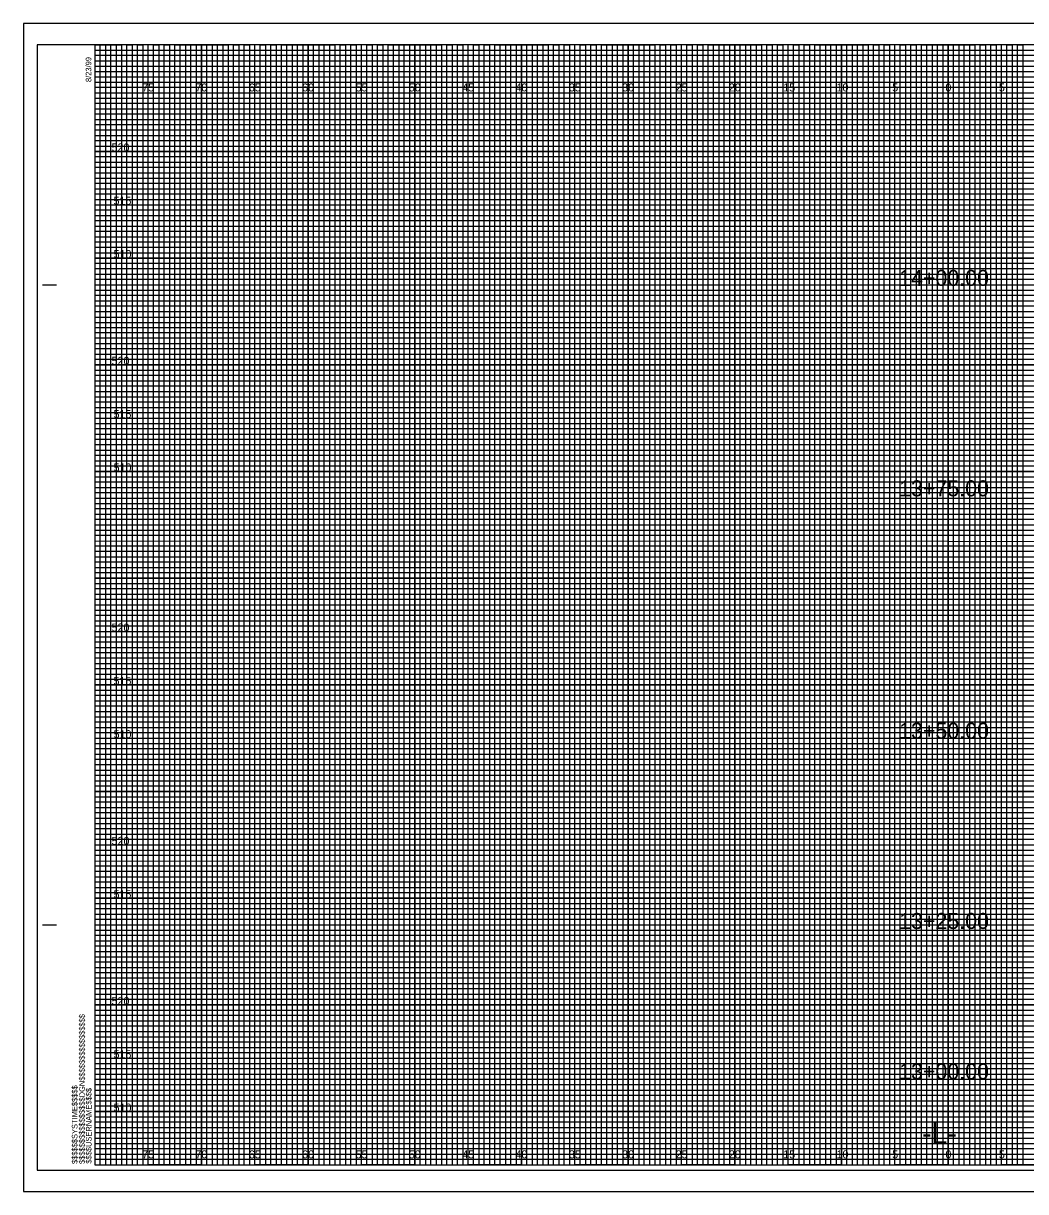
# Model space of a CAD drawing. Extents: x -7 to 181, y -2 to 107.
# Drawn here: x -6.7 to 87.2, y -2.5 to 107 of the extents above; entities that cross this region are included whole.
import ezdxf

# ---------------------------------------------------------------- set-up
doc = ezdxf.new("R2010")
doc.units = 0
for name, color, linetype in [('Prop XS Alignment Label', 7, 'Continuous'), ('Prop XS Elevation Labels', 7, 'Continuous'), ('Prop XS Offset Labels', 7, 'Continuous'), ('Prop XS Station Labels', 7, 'Continuous'), ('Sheet Cross Section CELL', 7, 'Continuous'), ('Sheet Cross Section Grid Major CELL', 7, 'Continuous'), ('Sheet Cross Section Grid Middle CELL', 7, 'Continuous'), ('Sheet Cross Section Grid Minor 1 CELL', 7, 'Continuous'), ('Sheet Cross Section Grid Minor 2 CELL', 7, 'Continuous'), ('Sheet Cutting Line CELL', 7, 'Continuous'), ('Sheet DOT Grid CELL', 7, 'Continuous'), ('Sheet Plot Border Inside CELL', 7, 'Continuous'), ('Sheet Plot Border Outside CELL', 7, 'Continuous')]:
    doc.layers.add(name, color=color, linetype=linetype)

msp = doc.modelspace()

# ---------------------------------------------------------------- linework, layer by layer
at = {"layer": 'Sheet Cross Section CELL'}
for p, q in [((-4.9, 82.5), (-3.65, 82.5)), ((-4.85, 82.5), (-3.6, 82.5)), ((-4.9, 22.5), (-3.65, 22.5)), ((-4.85, 22.5), (-3.6, 22.5)), ((0, 0), (0, 0)), ((0, 0), (0, 0)), ((0, 0), (0, 0)), ((0, 0), (0, 0)), ((0, 0), (0, 0)), ((0, 0), (0, 0)), ((0, 0), (0, 0))]:
    msp.add_line(p, q, dxfattribs=at)
msp.add_lwpolyline([(160, 105), (0, 105), (0, 0), (160, 0)], close=True, dxfattribs=at)
at = {"layer": 'Sheet Cross Section Grid Major CELL'}
for p, q in [((5, 105), (0, 105)), ((5, 0), (5, 105)), ((15, 105), (10, 105)), ((10, 105), (10, 0)), ((15, 0), (15, 105)), ((25, 105), (20, 105)), ((20, 105), (20, 0)), ((25, 0), (25, 105)), ((35, 105), (30, 105)), ((30, 105), (30, 0)), ((35, 0), (35, 105)), ((45, 105), (40, 105)), ((40, 105), (40, 0)), ((45, 0), (45, 105)), ((55, 105), (50, 105)), ((50, 105), (50, 0)), ((55, 0), (55, 105)), ((65, 105), (60, 105)), ((60, 105), (60, 0)), ((65, 0), (65, 105)), ((75, 105), (70, 105)), ((70, 105), (70, 0)), ((75, 0), (75, 105)), ((85, 105), (80, 105)), ((80, 105), (80, 0)), ((85, 0), (85, 105)), ((10, 0), (5, 0)), ((20, 0), (15, 0)), ((30, 0), (25, 0)), ((40, 0), (35, 0)), ((50, 0), (45, 0)), ((60, 0), (55, 0)), ((70, 0), (65, 0)), ((80, 0), (75, 0)), ((90, 0), (85, 0))]:
    msp.add_line(p, q, dxfattribs=at)
for points in [[(0, 100), (160, 100), (160, 95), (0, 95)], [(0, 90), (160, 90), (160, 85), (0, 85)], [(0, 80), (160, 80), (160, 75), (0, 75)], [(0, 70), (160, 70), (160, 65), (0, 65)], [(0, 60), (160, 60), (160, 55), (0, 55)], [(0, 50), (160, 50), (160, 45), (0, 45)], [(0, 40), (160, 40), (160, 35), (0, 35)], [(0, 30), (160, 30), (160, 25), (0, 25)], [(0, 20), (160, 20), (160, 15), (0, 15)], [(0, 10), (160, 10), (160, 5), (0, 5)]]:
    msp.add_lwpolyline(points, dxfattribs=at)
at = {"layer": 'Sheet Cross Section Grid Middle CELL'}
for points in [[(0, 105), (2.5, 105), (2.5, 0), (7.5, 0), (7.5, 105), (12.5, 105), (12.5, 0), (17.5, 0), (17.5, 105), (22.5, 105), (22.5, 0), (27.5, 0), (27.5, 105), (32.5, 105), (32.5, 0), (37.5, 0), (37.5, 105), (42.5, 105), (42.5, 0), (47.5, 0), (47.5, 105), (52.5, 105), (52.5, 0), (57.5, 0), (57.5, 105), (62.5, 105), (62.5, 0), (67.5, 0), (67.5, 105), (72.5, 105), (72.5, 0), (77.5, 0), (77.5, 105), (82.5, 105), (82.5, 0), (87.5, 0)], [(0, 102.5), (137.5, 102.5)], [(0, 92.5), (160, 92.5), (160, 97.5), (0, 97.5)], [(0, 82.5), (160, 82.5), (160, 87.5), (0, 87.5)], [(0, 72.5), (160, 72.5), (160, 77.5), (0, 77.5)], [(0, 62.5), (160, 62.5), (160, 67.5), (0, 67.5)], [(0, 52.5), (160, 52.5), (160, 57.5), (0, 57.5)], [(0, 42.5), (160, 42.5), (160, 47.5), (0, 47.5)], [(0, 32.5), (160, 32.5), (160, 37.5), (0, 37.5)], [(0, 22.5), (160, 22.5), (160, 27.5), (0, 27.5)], [(0, 12.5), (160, 12.5), (160, 17.5), (0, 17.5)], [(0, 2.5), (160, 2.5), (160, 7.5), (0, 7.5)]]:
    msp.add_lwpolyline(points, dxfattribs=at)
at = {"layer": 'Sheet Cross Section Grid Minor 1 CELL'}
for p, q in [((0, 104.5), (130, 104.5)), ((130, 103.99), (0, 103.99)), ((0, 103.99), (0, 103.5)), ((0, 103.5), (130, 103.5)), ((130, 102.95), (0, 102.95)), ((0, 102.95), (0, 102)), ((0, 102), (160, 102))]:
    msp.add_line(p, q, dxfattribs=at)
for points in [[(0, 101.5), (135, 101.5), (160, 101.5), (160, 101), (0, 101)], [(0, 100.5), (160, 100.5), (160, 99.5), (0, 99.5)], [(0, 99), (160, 99), (160, 98.5), (0, 98.49)], [(0, 98), (160, 98), (160, 97), (0, 97)], [(0, 96.5), (160, 96.5), (160, 96), (0, 96)], [(0, 95.5), (160, 95.5), (160, 94.5), (0, 94.5)], [(0, 94), (160, 94), (160, 93.5), (0, 93.5)], [(0, 93), (160, 93), (160, 92), (0, 92)], [(0, 91.5), (160, 91.5), (160, 91), (0, 91)], [(0, 90.5), (160, 90.5), (160, 89.5), (0, 89.5)], [(0, 89), (160, 89), (160, 88.5), (0, 88.5)], [(0, 88), (160, 88), (160, 86.98), (160, 86.5), (160, 86), (0, 86)], [(0, 87), (160, 87), (160, 86.5), (0, 86.5)], [(0, 85.5), (160, 85.5), (160, 84.5), (0, 84.52)], [(0, 84.52), (160, 84.5), (160, 84), (0, 84)], [(0, 83.5), (160, 83.5), (160, 83), (0, 83)], [(0, 82), (160, 82), (160, 81.5), (0, 81.5)], [(0, 81), (160, 81), (160, 80.5), (0, 80.5)], [(-0.04, 79.45), (160, 79.45), (160, 78.94), (-0.04, 78.94)], [(0, 78.5), (160, 78.5), (160, 78), (0, 78)], [(0, 77), (160, 77), (160, 76.5), (0, 76.5)], [(0, 76), (160, 76), (160, 75.5), (0, 75.5)], [(0, 74.5), (160, 74.5), (160, 74), (0, 74)], [(0, 73.5), (160, 73.5), (160, 73), (0, 73)], [(0, 72), (160, 72), (160, 71.5), (0, 71.5)], [(0, 71), (160, 71), (160, 70.5), (0, 70.5)], [(0, 69.5), (160, 69.5), (160, 68.99), (0, 69)], [(0, 68.5), (160, 68.5), (160, 68), (0, 68)], [(0, 67), (160, 67), (160, 66.5), (0, 66.5)], [(0, 66), (160, 66), (160, 65.5), (0, 65.5)], [(0, 64.5), (160, 64.5), (160, 64), (0, 64)], [(0, 63.5), (160, 63.5), (160, 63), (0, 63)], [(0, 62), (160, 62), (160, 61.5), (0, 61.5)], [(0, 61), (160, 61), (160, 60.5), (0, 60.5)], [(0, 59.5), (160, 59.5), (160, 59), (0, 59)], [(0, 58.5), (160.03, 58.45), (160, 58), (0, 58)], [(0, 57), (160, 57), (160, 56.5), (0, 56.5)], [(0, 56), (160, 56), (160, 55.5), (0, 55.5)], [(0, 54.5), (160, 54.5), (160, 54), (0, 54)], [(0, 53.5), (160, 53.5), (160, 53), (0, 53)], [(0, 52), (160, 52), (160, 51.5), (0, 51.5)], [(0, 51), (160, 51), (160, 50.5), (0, 50.5)], [(0, 49.5), (160, 49.5), (160, 49), (0, 49)], [(0, 48.5), (160, 48.5), (160, 48), (0, 48)], [(0, 47), (160, 47), (160, 46.5), (0, 46.5)], [(0, 46), (160, 46), (160, 45.5), (0, 45.5)], [(0, 44.5), (160, 44.5), (160, 44), (0, 44)], [(0, 43.5), (160, 43.5), (160, 43), (0, 43)], [(0, 42), (160, 42), (160, 41.5), (0, 41.5)], [(0, 41), (160, 41), (160, 40.5), (0, 40.5)], [(0, 39.5), (160, 39.5), (160, 38.99), (0, 39)], [(0, 38.5), (160, 38.5), (160, 38), (0, 38)], [(0, 37), (160, 37), (160, 36.5), (0, 36.5)], [(0, 36), (160, 36), (160, 35.5), (0, 35.5)], [(0, 34.5), (160, 34.5), (160, 34), (0, 34)], [(0, 33.5), (160, 33.5), (160, 33), (0, 33)], [(0, 32), (160, 32), (160, 31.5), (0, 31.5)], [(0, 31), (160, 31), (160, 30.5), (0, 30.5)], [(0, 29.5), (160, 29.5), (160, 29), (0, 29)], [(0, 28.5), (160.03, 28.46), (160, 28), (0, 28)], [(0, 27), (160, 27), (160, 26.5), (0, 26.5)], [(0, 26), (160, 26), (160, 25.5), (0, 25.5)], [(0, 24.5), (160, 24.5), (160, 24), (0, 24)], [(0, 23.5), (160, 23.5), (160, 23), (0, 23)], [(0, 22), (160, 22), (160, 21.5), (0, 21.5)], [(0, 21), (160, 21), (160, 20.5), (0, 20.5)], [(0, 19.5), (160, 19.5), (160, 19), (0, 19)], [(0, 18.5), (160, 18.5), (160, 18), (0, 18)], [(0, 17), (160, 17), (160, 16.5), (0, 16.5)], [(0, 16), (160, 16), (160, 15.5), (0, 15.5)], [(0, 14.5), (160, 14.5), (160, 14), (0, 14)], [(0, 13.5), (160, 13.5), (160, 13), (0, 13)], [(0, 12), (160, 12), (160, 11.5), (0, 11.5)], [(0, 11), (160, 11), (160, 10.5), (0, 10.5)], [(0, 9.5), (160, 9.5), (160, 9), (0, 9)], [(0, 8.5), (160, 8.5), (160, 8), (0, 8)], [(0, 7), (160, 7), (160, 6.5), (0, 6.5)], [(0, 6), (160, 6), (160, 5.5), (0, 5.5)], [(0, 4.5), (160, 4.5), (160, 4), (0, 4)], [(0, 3.5), (160, 3.5), (160, 3), (0, 3)], [(0, 2), (160, 2), (160, 1.5), (0, 1.5)], [(0, 1), (160, 1), (160, 0.5), (0, 0.5)]]:
    msp.add_lwpolyline(points, dxfattribs=at)
at = {"layer": 'Sheet Cross Section Grid Minor 2 CELL'}
for points in [[(0, 0), (0.5, 0), (0.5, 105), (1, 105), (1, 0)], [(1, 0), (1.5, 0), (1.5, 105), (2, 105), (2, 0)], [(2.5, 0), (3, 0), (3, 105), (3.5, 105), (3.5, 0)], [(3.5, 0), (4, 0), (4, 105), (4.5, 105), (4.5, 0)], [(5, 0), (5.5, 0), (5.5, 105), (6, 105), (6, 0)], [(6, 0), (6.5, 0), (6.5, 105), (7, 105), (7, 0)], [(7.5, 0), (8, 0), (8, 105), (8.5, 105), (8.5, 0)], [(8.5, 0), (9, 0), (9, 105), (9.5, 105), (9.5, 0)], [(10, 0), (10.5, 0), (10.5, 105), (11, 105), (11, 0)], [(11, 0), (11.5, 0), (11.5, 105), (12, 105), (12, 0)], [(12.5, 0), (13, 0), (13, 105), (13.5, 105), (13.5, 0)], [(13.5, 0), (14, 0), (14, 105), (14.5, 105), (14.5, 0)], [(15, 0), (15.5, 0), (15.5, 105), (16, 105), (16, 0)], [(16, 0), (16.5, 0), (16.5, 105), (17, 105), (17, 0)], [(17.5, 0), (18, 0), (18, 105), (18.5, 105), (18.5, 0)], [(18.5, 0), (19, 0), (19, 105), (19.5, 105), (19.5, 0)], [(20, 0), (20.5, 0), (20.5, 105), (21, 105), (21, 0)], [(21, 0), (21.5, 0), (21.5, 105), (22, 105), (22, 0)], [(22.5, 0), (23, 0), (23, 105), (23.5, 105), (23.5, 0)], [(23.5, 0), (24, 0), (24, 105), (24.5, 105), (24.5, 0)], [(25, 0), (25.5, 0), (25.5, 105), (26, 105), (26, 0)], [(26, 0), (26.5, 0), (26.5, 105), (27, 105), (27, 0)], [(27.5, 0), (28, 0), (28, 105), (28.5, 105), (28.5, 0)], [(28.5, 0), (29, 0), (29, 105), (29.5, 105), (29.5, 0)], [(30, 0), (30.5, 0), (30.5, 105), (31, 105), (31, 0)], [(31, 0), (31.5, 0), (31.5, 105), (32, 105), (32, 0)], [(32.5, 0), (33, 0), (33, 105), (33.5, 105), (33.5, 0)], [(33.5, 0), (34, 0), (34, 105), (34.5, 105), (34.5, 0)], [(35, 0), (35.5, 0), (35.5, 105), (36, 105), (36, 0)], [(36, 0), (36.5, 0), (36.5, 105), (37, 105), (37, 0)], [(37.5, 0), (38, 0), (38, 105), (38.5, 105), (38.5, 0)], [(38.5, 0), (39, 0), (39, 105), (39.5, 105), (39.5, 0)], [(40, 0), (40.5, 0), (40.5, 105), (41, 105), (41, 0)], [(41, 0), (41.5, 0), (41.5, 105), (42, 105), (42, 0)], [(42.5, 0), (43, 0), (43, 105), (43.5, 105), (43.5, 0)], [(43.5, 0), (44, 0), (44, 105), (44.5, 105), (44.5, 0)], [(45, 0), (45.5, 0), (45.5, 105), (46, 105), (46, 0)], [(46, 0), (46.5, 0), (46.5, 105), (47, 105), (47, 0)], [(47.5, 0), (48, 0), (48, 105), (48.5, 105), (48.5, 0)], [(48.5, 0), (49, 0), (49, 105), (49.5, 105), (49.5, 0)], [(50, 0), (50.5, 0), (50.5, 105), (51, 105), (51, 0)], [(51, 0), (51.5, 0), (51.5, 105), (52, 105), (52, 0)], [(52.5, 0), (53, 0), (53, 105), (53.5, 105), (53.5, 0)], [(53.5, 0), (54, 0), (54, 105), (54.5, 105), (54.5, 0)], [(55, 0), (55.5, 0), (55.5, 105), (56, 105), (56, 0)], [(56, 0), (56.5, 0), (56.5, 105), (57, 105), (57, 0)], [(57.5, 0), (58, 0), (58, 105), (58.5, 105), (58.5, 0)], [(58.5, 0), (59, 0), (59, 105), (59.5, 105), (59.5, 0)], [(60, 0), (60.5, 0), (60.5, 105), (61, 105), (61, 0)], [(61, 0), (61.5, 0), (61.5, 105), (62, 105), (62, 0)], [(62.5, 0), (63, 0), (63, 105), (63.5, 105), (63.5, 0)], [(63.5, 0), (64, 0), (64, 105), (64.5, 105), (64.5, 0)], [(65, 0), (65.5, 0), (65.5, 105), (66, 105), (66, 0)], [(66, 0), (66.5, 0), (66.5, 105), (67, 105), (67, 0)], [(67.5, 0), (68, 0), (68, 105), (68.5, 105), (68.5, 0)], [(68.5, 0), (69, 0), (69, 105), (69.5, 105), (69.5, 0)], [(70, 0), (70.5, 0), (70.5, 105), (71, 105), (71, 0)], [(71, 0), (71.5, 0), (71.5, 105), (72, 105), (72, 0)], [(72.5, 0), (73, 0), (73, 105), (73.5, 105), (73.5, 0)], [(73.5, 0), (74, 0), (74, 105), (74.5, 105), (74.5, 0)], [(75, 0), (75.5, 0), (75.5, 105), (76, 105), (76, 0)], [(76, 0), (76.5, 0), (76.5, 105), (77, 105), (77, 0)], [(77.5, 0), (78, 0), (78, 105), (78.5, 105), (78.5, 0)], [(78.5, 0), (79, 0), (79, 105), (79.5, 105), (79.5, 0)], [(80, 0), (80.5, 0), (80.5, 105), (81, 105), (81, 0)], [(81, 0), (81.5, 0), (81.5, 105), (82, 105), (82, 0)], [(82.5, 0), (83, 0), (83, 105), (83.5, 105), (83.5, 0)], [(83.5, 0), (84, 0), (84, 105), (84.5, 105), (84.5, 0)], [(85, 0), (85.5, 0), (85.5, 105), (86, 105), (86, 0)], [(86, 0), (86.5, 0), (86.5, 105), (87, 105), (87, 0)]]:
    msp.add_lwpolyline(points, dxfattribs=at)
at = {"layer": 'Sheet Cutting Line CELL'}
for p, q in [((161.65, 107), (-6.7, 107)), ((-6.7, 107), (-6.7, -2.5)), ((-6.7, -2.5), (161.65, -2.5))]:
    msp.add_line(p, q, dxfattribs=at)
at = {"layer": 'Sheet DOT Grid CELL'}
for p, q in [((5, 0), (5, 105)), ((10, 0), (10, 105)), ((15, 0), (15, 105)), ((20, 0), (20, 105)), ((25, 0), (25, 105)), ((30, 0), (30, 105)), ((35, 0), (35, 105)), ((40, 0), (40, 105)), ((45, 0), (45, 105)), ((50, 0), (50, 105)), ((55, 0), (55, 105)), ((60, 0), (60, 105)), ((65, 0), (65, 105)), ((70, 0), (70, 105)), ((75, 0), (75, 105)), ((80, 0), (80, 105)), ((85, 0), (85, 105)), ((0, 100), (160, 100)), ((0, 95), (160, 95)), ((0, 90), (160, 90)), ((0, 85), (160, 85)), ((0, 80), (160, 80)), ((0, 75), (160, 75)), ((0, 70), (160, 70)), ((0, 65), (160, 65)), ((0, 60), (160, 60)), ((0, 55), (160, 55)), ((0, 50), (160, 50)), ((0, 45), (160, 45)), ((0, 40), (160, 40)), ((0, 35), (160, 35)), ((0, 30), (160, 30)), ((0, 25), (160, 25)), ((0, 20), (160, 20)), ((0, 15), (160, 15)), ((0, 10), (160, 10)), ((0, 5), (160, 5))]:
    msp.add_line(p, q, dxfattribs=at)
at = {"layer": 'Sheet Plot Border Inside CELL'}
msp.add_lwpolyline([(-5.4, -0.5), (161.2, -0.5), (161.2, 105), (-5.4, 105)], close=True, dxfattribs=at)
at = {"layer": 'Sheet Plot Border Outside CELL'}
msp.add_lwpolyline([(-6.7, -2.5), (161.65, -2.5), (161.65, 107), (-6.7, 107)], close=True, dxfattribs=at)

# ---------------------------------------------------------------- texts
at = {"layer": 'Prop XS Alignment Label'}
msp.add_text('-L-', height=2, dxfattribs=at).set_placement((77.53, 2))
at = {"layer": 'Prop XS Elevation Labels'}
for s, p in [('520', (1.57, 95)), ('515', (1.75, 90)), ('510', (1.76, 85)), ('520', (1.57, 75)), ('515', (1.75, 70)), ('510', (1.76, 65)), ('520', (1.57, 50)), ('515', (1.75, 45)), ('510', (1.76, 40)), ('520', (1.57, 30)), ('515', (1.75, 25)), ('520', (1.57, 15)), ('515', (1.75, 10)), ('510', (1.76, 5))]:
    msp.add_text(s, height=0.75, dxfattribs=at).set_placement(p)
at = {"layer": 'Prop XS Offset Labels'}
for s, p in [('75', (4.44, 100.62)), ('70', (9.43, 100.62)), ('65', (14.44, 100.62)), ('60', (19.43, 100.62)), ('55', (24.44, 100.62)), ('50', (29.43, 100.62)), ('45', (34.44, 100.62)), ('40', (39.43, 100.62)), ('35', (44.44, 100.62)), ('30', (49.43, 100.62)), ('25', (54.44, 100.62)), ('20', (59.43, 100.62)), ('15', (64.53, 100.62)), ('10', (69.52, 100.62)), ('5', (74.74, 100.62)), ('0', (79.73, 100.62)), ('0', (79.73, 100.62)), ('5', (84.74, 100.62)), ('75', (4.44, 0.62)), ('70', (9.43, 0.62)), ('65', (14.44, 0.62)), ('60', (19.43, 0.62)), ('55', (24.44, 0.62)), ('50', (29.43, 0.62)), ('45', (34.44, 0.62)), ('40', (39.43, 0.62)), ('35', (44.44, 0.62)), ('30', (49.43, 0.62)), ('25', (54.44, 0.62)), ('20', (59.43, 0.62)), ('15', (64.53, 0.62)), ('10', (69.52, 0.62)), ('5', (74.74, 0.62)), ('0', (79.73, 0.62)), ('0', (79.73, 0.62)), ('5', (84.74, 0.62))]:
    msp.add_text(s, height=0.75, dxfattribs=at).set_placement(p)
at = {"layer": 'Prop XS Station Labels'}
for s, p in [('14+00.00', (75.39, 82.39)), ('13+75.00', (75.39, 62.67)), ('13+50.00', (75.39, 39.95)), ('13+25.00', (75.39, 22.12)), ('13+00.00', (75.39, 8.02))]:
    msp.add_text(s, height=1.5, dxfattribs=at).set_placement(p)
at = {"layer": 'Sheet Cross Section CELL'}
for s, p in [('8/23/99', (-0.33, 101.5)), ('$$$$$$$$$$$$$$$$DGN$$$$$$$$$$$$$$$$', (-0.94, 0.09)), ('$$$$$$SYSTIME$$$$$', (-1.63, 0.09)), ('$$$$USERNAME$$$$', (-0.31, 0.12))]:
    msp.add_text(s, height=0.525, rotation=90, dxfattribs=at).set_placement(p)

doc.saveas('drawing.dxf')
